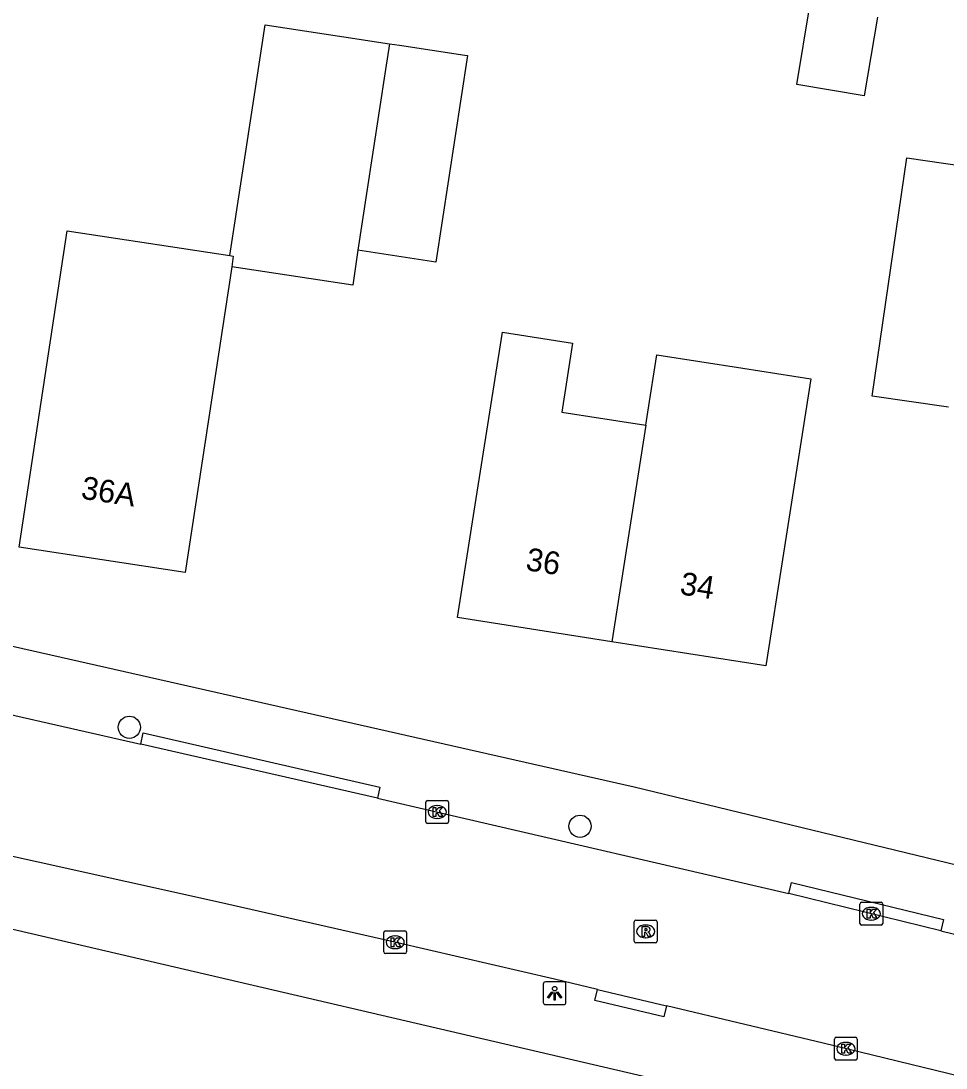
# Model space of a CAD drawing. Extents: x 161486 to 162249, y 379484 to 380829.
# Drawn here: x 161920.56 to 161961.17, y 380395.25 to 380441.2 of the extents above; entities that cross this region are included whole.
import ezdxf

# ---------------------------------------------------------------- set-up
doc = ezdxf.new("R2010")
doc.units = 0
for name, color, linetype in [('IMGEO_Boom', 7, 'Continuous'), ('IMGEO_Kolk', 7, 'Continuous'), ('IMGEO_Lichtpunt', 7, 'Continuous'), ('IMGEO_Pand', 7, 'Continuous'), ('IMGEO_Pand_nummerreeks', 7, 'Continuous'), ('IMGEO_Rijbaan_lokaal_open', 7, 'Continuous'), ('IMGEO_Rioolput', 7, 'Continuous'), ('IMGEO_Voetpad_open', 7, 'Continuous')]:
    doc.layers.add(name, color=color, linetype=linetype)

msp = doc.modelspace()

# ---------------------------------------------------------------- linework, layer by layer
at = {"layer": 'IMGEO_Boom'}
for centre in [(161925.322, 380410.202), (161945.101, 380405.857)]:
    msp.add_circle(centre, 0.489, dxfattribs=at)
at = {"layer": 'IMGEO_Kolk'}
for p, q in [((161938.407, 380406.984), (161939.259, 380406.984)), ((161938.332, 380406.058), (161938.332, 380406.91)), ((161938.82, 380406.764), (161938.845, 380406.764)), ((161939.333, 380406.91), (161939.333, 380406.058)), ((161938.843, 380406.204), (161938.818, 380406.204)), ((161939.259, 380405.984), (161938.407, 380405.984)), ((161957.385, 380401.593), (161957.385, 380402.445)), ((161957.46, 380402.519), (161958.312, 380402.519)), ((161958.386, 380402.445), (161958.386, 380401.593)), ((161957.873, 380402.299), (161957.898, 380402.299)), ((161958.312, 380401.519), (161957.46, 380401.519)), ((161957.896, 380401.739), (161957.871, 380401.739)), ((161936.487, 380400.341), (161936.487, 380401.193)), ((161936.562, 380401.267), (161937.414, 380401.267)), ((161936.975, 380401.047), (161937, 380401.047)), ((161937.488, 380401.193), (161937.488, 380400.341)), ((161937.414, 380400.267), (161936.562, 380400.267)), ((161936.998, 380400.487), (161936.973, 380400.487)), ((161956.27, 380395.668), (161956.27, 380396.52)), ((161956.345, 380396.594), (161957.197, 380396.594)), ((161956.758, 380396.374), (161956.783, 380396.374)), ((161957.271, 380396.52), (161957.271, 380395.668)), ((161957.197, 380395.594), (161956.345, 380395.594)), ((161956.781, 380395.814), (161956.756, 380395.814))]:
    msp.add_line(p, q, dxfattribs=at)
for points in [[(161938.407, 380406.984), (161939.259, 380406.984)], [(161938.332, 380406.058), (161938.332, 380406.91)], [(161938.653, 380406.684), (161938.776, 380406.684), (161938.776, 380406.533), (161938.906, 380406.684), (161939.07, 380406.684), (161938.924, 380406.533), (161939.077, 380406.284), (161938.925, 380406.284), (161938.84, 380406.448), (161938.776, 380406.381), (161938.776, 380406.284), (161938.653, 380406.284), (161938.653, 380406.684)], [(161939.333, 380406.91), (161939.333, 380406.058)], [(161939.259, 380405.984), (161938.407, 380405.984)], [(161957.385, 380401.593), (161957.385, 380402.445)], [(161957.46, 380402.519), (161958.312, 380402.519)], [(161958.386, 380402.445), (161958.386, 380401.593)], [(161957.706, 380402.219), (161957.829, 380402.219), (161957.829, 380402.068), (161957.959, 380402.219), (161958.123, 380402.219), (161957.977, 380402.068), (161958.13, 380401.819), (161957.978, 380401.819), (161957.893, 380401.983), (161957.829, 380401.916), (161957.829, 380401.819), (161957.706, 380401.819), (161957.706, 380402.219)], [(161958.312, 380401.519), (161957.46, 380401.519)], [(161936.487, 380400.341), (161936.487, 380401.193)], [(161936.562, 380401.267), (161937.414, 380401.267)], [(161936.808, 380400.967), (161936.931, 380400.967), (161936.931, 380400.816), (161937.061, 380400.967), (161937.225, 380400.967), (161937.079, 380400.816), (161937.232, 380400.567), (161937.08, 380400.567), (161936.995, 380400.731), (161936.931, 380400.664), (161936.931, 380400.567), (161936.808, 380400.567), (161936.808, 380400.967)], [(161937.488, 380401.193), (161937.488, 380400.341)], [(161937.414, 380400.267), (161936.562, 380400.267)], [(161956.27, 380395.668), (161956.27, 380396.52)], [(161956.345, 380396.594), (161957.197, 380396.594)], [(161957.271, 380396.52), (161957.271, 380395.668)], [(161956.591, 380396.294), (161956.714, 380396.294), (161956.714, 380396.143), (161956.844, 380396.294), (161957.008, 380396.294), (161956.862, 380396.143), (161957.015, 380395.894), (161956.863, 380395.894), (161956.778, 380396.058), (161956.714, 380395.991), (161956.714, 380395.894), (161956.591, 380395.894), (161956.591, 380396.294)], [(161957.197, 380395.594), (161956.345, 380395.594)]]:
    msp.add_lwpolyline(points, dxfattribs=at)
for centre, start, end in [((161938.409, 380406.908), 91.552, 178.448), ((161938.409, 380406.908), 91.552, 178.448), ((161939.257, 380406.908), 1.552, 88.448), ((161939.257, 380406.908), 1.552, 88.448), ((161938.409, 380406.06), 181.552, 268.448), ((161938.409, 380406.06), 181.552, 268.448), ((161939.257, 380406.06), 271.552, 358.448), ((161939.257, 380406.06), 271.552, 358.448), ((161957.462, 380402.443), 91.552, 178.448), ((161957.462, 380402.443), 91.552, 178.448), ((161958.31, 380402.443), 1.552, 88.448), ((161958.31, 380402.443), 1.552, 88.448), ((161957.462, 380401.595), 181.552, 268.448), ((161957.462, 380401.595), 181.552, 268.448), ((161958.31, 380401.595), 271.552, 358.448), ((161958.31, 380401.595), 271.552, 358.448), ((161936.564, 380401.191), 91.552, 178.448), ((161936.564, 380401.191), 91.552, 178.448), ((161937.412, 380401.191), 1.552, 88.448), ((161937.412, 380401.191), 1.552, 88.448), ((161936.564, 380400.343), 181.552, 268.448), ((161936.564, 380400.343), 181.552, 268.448), ((161937.412, 380400.343), 271.552, 358.448), ((161937.412, 380400.343), 271.552, 358.448), ((161956.347, 380396.518), 91.552, 178.448), ((161956.347, 380396.518), 91.552, 178.448), ((161957.195, 380396.518), 1.552, 88.448), ((161957.195, 380396.518), 1.552, 88.448), ((161956.347, 380395.67), 181.552, 268.448), ((161956.347, 380395.67), 181.552, 268.448), ((161957.195, 380395.67), 271.552, 358.448), ((161957.195, 380395.67), 271.552, 358.448)]:
    msp.add_arc(centre, 0.0765, start, end, dxfattribs=at)
for centre, major_axis, ratio, start_param, end_param in [((161938.819, 380406.484), (-0.387, 0.002), 0.722429, 4.712389, 7.853982), ((161938.844, 380406.484), (-0.39, 0.002), 0.717154, 1.570796, 4.712389), ((161957.872, 380402.019), (-0.387, 0.002), 0.722429, 4.712389, 7.853982), ((161957.897, 380402.019), (-0.39, 0.002), 0.717154, 1.570796, 4.712389), ((161936.974, 380400.767), (-0.387, 0.002), 0.722429, 4.712389, 7.853982), ((161936.999, 380400.767), (-0.39, 0.002), 0.717154, 1.570796, 4.712389), ((161956.757, 380396.094), (-0.387, 0.002), 0.722429, 4.712389, 7.853982), ((161956.782, 380396.094), (-0.39, 0.002), 0.717154, 1.570796, 4.712389)]:
    msp.add_ellipse(centre, major_axis=major_axis, ratio=ratio, start_param=start_param, end_param=end_param, dxfattribs=at)
at = {"layer": 'IMGEO_Lichtpunt'}
for p, q in [((161943.488, 380398.934), (161943.488, 380398.127)), ((161943.488, 380398.934), (161943.488, 380398.127)), ((161944.39, 380399.029), (161943.582, 380399.029)), ((161944.39, 380399.029), (161943.582, 380399.029)), ((161944.484, 380398.127), (161944.484, 380398.934)), ((161944.484, 380398.127), (161944.484, 380398.934)), ((161943.582, 380398.033), (161944.39, 380398.033)), ((161943.582, 380398.033), (161944.39, 380398.033))]:
    msp.add_line(p, q, dxfattribs=at)
for points in [[(161943.862, 380398.598), (161943.901, 380398.57), (161943.713, 380398.308), (161943.675, 380398.335), (161943.862, 380398.598)], [(161943.964, 380398.55), (161944.011, 380398.55), (161944.011, 380398.228), (161943.964, 380398.228), (161943.964, 380398.55)], [(161944.074, 380398.57), (161944.112, 380398.597), (161944.299, 380398.335), (161944.26, 380398.307), (161944.074, 380398.57)]]:
    msp.add_lwpolyline(points, dxfattribs=at)
msp.add_circle((161943.987, 380398.732), 0.0994, dxfattribs=at)
for centre, start, end in [((161943.582, 380398.934), 90, 180), ((161943.582, 380398.934), 90, 180), ((161944.39, 380398.934), 0, 90), ((161944.39, 380398.934), 0, 90), ((161943.582, 380398.127), 180, 270), ((161943.582, 380398.127), 180, 270), ((161944.39, 380398.127), 270, 0), ((161944.39, 380398.127), 270, 360)]:
    msp.add_arc(centre, 0.0946, start, end, dxfattribs=at)
at = {"layer": 'IMGEO_Pand'}
for points in [[(161958.152, 380441.367), (161957.571, 380437.916), (161954.612, 380438.414), (161955.193, 380441.865)], [(161929.731, 380430.899), (161930.806, 380437.959), (161931.274, 380441.032), (161933.874, 380440.636), (161934.731, 380440.506), (161936.736, 380440.2)], [(161936.736, 380440.2), (161937.17, 380440.134), (161940.05, 380439.696), (161940.159, 380439.679), (161938.778, 380430.612), (161935.355, 380431.133)], [(161936.736, 380440.2), (161936.563, 380439.067), (161935.736, 380433.633), (161935.355, 380431.133)], [(161961.278, 380424.245), (161957.926, 380424.729), (161959.439, 380435.198), (161962.868, 380434.7)], [(161929.812, 380430.412), (161927.768, 380416.991), (161920.477, 380418.101), (161922.592, 380431.987), (161929.731, 380430.899)], [(161929.731, 380430.899), (161929.883, 380430.876), (161929.812, 380430.412)], [(161935.355, 380431.133), (161935.122, 380429.603), (161929.812, 380430.412)], [(161946.49, 380413.957), (161939.727, 380415.018), (161940.502, 380419.958), (161941.693, 380427.544), (161944.773, 380427.061), (161944.298, 380424.033), (161947.982, 380423.455)], [(161947.982, 380423.455), (161948.072, 380424.03), (161948.467, 380426.549), (161952.245, 380425.957), (161955.23, 380425.489), (161954.029, 380417.835), (161953.254, 380412.895), (161946.49, 380413.957)], [(161947.982, 380423.455), (161946.49, 380413.957)]]:
    msp.add_lwpolyline(points, dxfattribs=at)
at = {"layer": 'IMGEO_Rijbaan_lokaal_open'}
for points in [[(161918.642, 380411.053), (161919.635, 380410.863), (161925.821, 380409.464)], [(161936.208, 380407.084), (161925.821, 380409.464)], [(161936.208, 380407.084), (161938.867, 380406.475), (161954.267, 380402.904)], [(161945.872, 380398.697), (161943.985, 380399.147), (161937.036, 380400.757), (161929.239, 380402.532), (161917.277, 380405.18), (161910.844, 380406.568)], [(161960.942, 380401.274), (161954.267, 380402.904)], [(161960.942, 380401.274), (161968.34, 380399.467), (161979.053, 380396.866), (161979.272, 380396.825), (161983.129, 380395.815)], [(161945.872, 380398.697), (161948.892, 380397.978)], [(161978.066, 380390.834), (161975.107, 380391.568), (161970.418, 380392.723), (161968.876, 380393.146), (161955.767, 380396.34), (161948.892, 380397.978)]]:
    msp.add_lwpolyline(points, dxfattribs=at)
at = {"layer": 'IMGEO_Rioolput'}
for p, q in [((161947.481, 380400.815), (161947.481, 380401.667)), ((161947.556, 380401.741), (161948.408, 380401.741)), ((161947.969, 380401.521), (161947.994, 380401.521)), ((161948.482, 380401.667), (161948.482, 380400.815)), ((161947.992, 380400.961), (161947.967, 380400.961)), ((161948.408, 380400.741), (161947.556, 380400.741))]:
    msp.add_line(p, q, dxfattribs=at)
for points in [[(161947.481, 380400.815), (161947.481, 380401.667)], [(161947.556, 380401.741), (161948.408, 380401.741)], [(161948.07, 380401.439), (161947.818, 380401.441), (161947.818, 380401.041)], [(161948.482, 380401.667), (161948.482, 380400.815)], [(161947.818, 380401.041), (161947.942, 380401.041), (161947.942, 380401.203), (161947.953, 380401.203)], [(161947.996, 380401.36), (161947.942, 380401.36), (161947.942, 380401.279)], [(161947.942, 380401.279), (161947.994, 380401.279)], [(161948, 380401.174), (161948.071, 380401.041), (161948.211, 380401.041), (161948.146, 380401.167)], [(161948.408, 380400.741), (161947.556, 380400.741)]]:
    msp.add_lwpolyline(points, dxfattribs=at)
for centre, radius, start, end in [((161947.558, 380401.665), 0.0765, 91.552, 178.448), ((161947.558, 380401.665), 0.0765, 91.552, 178.448), ((161948.069, 380401.329), 0.109, 350.3612, 89.416), ((161948.406, 380401.665), 0.0765, 1.552, 88.448), ((161948.406, 380401.665), 0.0765, 1.552, 88.448), ((161947.952, 380401.15), 0.0533, 26.0293, 88.6989), ((161947.978, 380401.468), 0.19, 274.7715, 282.9687), ((161948.002, 380401.264), 0.0964, 77.0061, 93.1865), ((161948.016, 380401.321), 0.0378, 276.6634, 79.6772), ((161948.067, 380401.329), 0.112, 277.5842, 350.9817), ((161948.051, 380401.114), 0.108, 29.5134, 73.7905), ((161947.558, 380400.817), 0.0765, 181.552, 268.448), ((161947.558, 380400.817), 0.0765, 181.552, 268.448), ((161948.406, 380400.817), 0.0765, 271.552, 358.448), ((161948.406, 380400.817), 0.0765, 271.552, 358.448)]:
    msp.add_arc(centre, radius, start, end, dxfattribs=at)
for centre, major_axis, ratio, start_param, end_param in [((161947.968, 380401.241), (-0.387, 0.002), 0.722429, 4.712389, 7.853982), ((161947.993, 380401.241), (-0.39, 0.002), 0.717154, 1.570796, 4.712389)]:
    msp.add_ellipse(centre, major_axis=major_axis, ratio=ratio, start_param=start_param, end_param=end_param, dxfattribs=at)
at = {"layer": 'IMGEO_Voetpad_open'}
for points in [[(161917.857, 380414.284), (161947.471, 380407.585), (161980.058, 380399.699)], [(161925.821, 380409.464), (161925.926, 380409.952), (161936.313, 380407.572), (161936.208, 380407.084)], [(162198.701, 380353.085), (162194.98, 380353.343), (162177.85, 380354.254), (162167.435, 380355.075), (162143.228, 380356.612), (162124.747, 380358.414), (162101.438, 380361.321), (162078.957, 380365.04), (162051.567, 380370.414), (162025.006, 380376.148), (162000, 380382.025), (161995.099, 380383.252), (161959.315, 380392.214), (161910.21, 380403.651), (161910.18, 380403.657)], [(161954.267, 380402.904), (161954.379, 380403.391), (161961.054, 380401.761), (161960.942, 380401.274)], [(161948.892, 380397.978), (161948.777, 380397.492), (161945.757, 380398.211), (161945.872, 380398.697)]]:
    msp.add_lwpolyline(points, dxfattribs=at)

# ---------------------------------------------------------------- texts
at = {"layer": 'IMGEO_Pand_nummerreeks'}
for s, rotation, p in [('36A', 351.3426, (161923.161, 380420.241)), ('36', 351.079, (161942.682, 380417.104)), ('34', 351.079, (161949.446, 380416.043))]:
    msp.add_text(s, height=1, rotation=rotation, dxfattribs=at).set_placement(p)

doc.saveas('drawing.dxf')
